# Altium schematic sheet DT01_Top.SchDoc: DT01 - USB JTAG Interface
size A4; Organization: Altium Limited.; Address1: Level 3, 12a Rodborough Rd; Address2: Frenchs Forest 2086; Address3: NSW; Address4: AUSTRALIA; DocumentNumber: 1; Revision: 01; SheetNumber: 1; SheetTotal: 12; PageSetup: Record=PageOptions|CenterHorizontal=True|CenterVertical=True|PrintScale=0.50|XCorrection=1.00|YCorrection=1.00|PrintKind=0|BorderSize=5000000|LeftOffset=0|BottomOffset=0|Orientation=2|PaperLength=1000|PaperWidth=1000|Scale=100|PaperSource=7|PrintQuality=600|MediaType=1|DitherType=10|PaperKind=A3 (297 x 420 mm)|PrintScaleMode=1
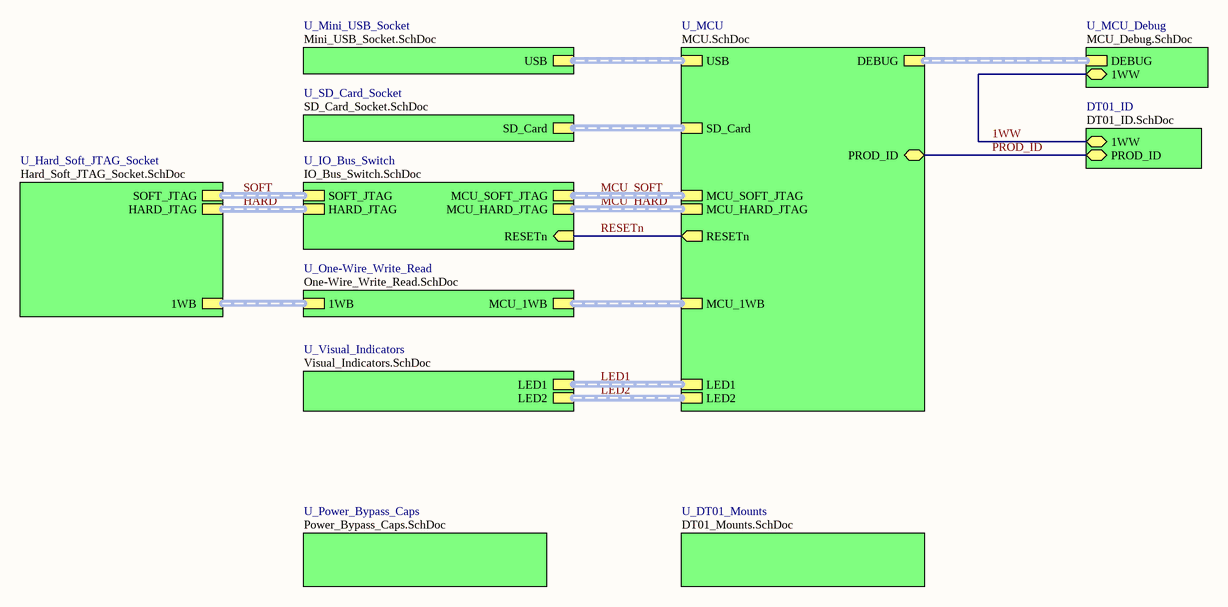
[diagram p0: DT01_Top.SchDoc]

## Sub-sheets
DT01_ID = DT01_ID.SchDoc: PROD_ID (bidir), 1WW (bidir)
U_DT01_Mounts = DT01_Mounts.SchDoc: no entries
U_Hard_Soft_JTAG_Socket = Hard_Soft_JTAG_Socket.SchDoc: 1WB (harness 1WB_Write_Read), SOFT_JTAG (harness JTAG), HARD_JTAG (harness JTAG)
U_IO_Bus_Switch = IO_Bus_Switch.SchDoc: SOFT_JTAG (harness JTAG), HARD_JTAG (harness JTAG), MCU_SOFT_JTAG (harness JTAG), MCU_HARD_JTAG (harness JTAG), RESETn (in)
U_MCU = MCU.SchDoc: USB (harness USB), RESETn (out), DEBUG (harness LOCAL_JTAG), MCU_SOFT_JTAG (harness JTAG), MCU_HARD_JTAG (harness JTAG), MCU_1WB (harness MCU_1WB_R_W), LED1 (harness RGB_LED), LED2 (harness RGB_LED), PROD_ID (bidir), SD_Card (harness SD Card)
U_MCU_Debug = MCU_Debug.SchDoc: DEBUG (harness LOCAL_JTAG), 1WW (bidir)
U_Mini_USB_Socket = Mini_USB_Socket.SchDoc: USB (harness USB)
U_One-Wire_Write_Read = One-Wire_Write_Read.SchDoc: 1WB (harness 1WB_Write_Read), MCU_1WB (harness MCU_1WB_R_W)
U_Power_Bypass_Caps = Power_Bypass_Caps.SchDoc: no entries
U_SD_Card_Socket = SD_Card_Socket.SchDoc: SD_Card (harness SD Card)
U_Visual_Indicators = Visual_Indicators.SchDoc: LED1 (harness RGB_LED), LED2 (harness RGB_LED)

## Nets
1WW: sheet DT01_ID/1WW, sheet U_MCU_Debug/1WW
PROD_ID: sheet U_MCU/PROD_ID, sheet DT01_ID/PROD_ID
RESETn: sheet U_MCU/RESETn, sheet U_IO_Bus_Switch/RESETn

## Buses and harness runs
harness HARD = sheet U_Hard_Soft_JTAG_Socket/HARD_JTAG = sheet U_IO_Bus_Switch/HARD_JTAG
harness LED1 = sheet U_MCU/LED1 = sheet U_Visual_Indicators/LED1
harness LED2 = sheet U_MCU/LED2 = sheet U_Visual_Indicators/LED2
harness MCU_HARD = sheet U_IO_Bus_Switch/MCU_HARD_JTAG = sheet U_MCU/MCU_HARD_JTAG
harness MCU_SOFT = sheet U_IO_Bus_Switch/MCU_SOFT_JTAG = sheet U_MCU/MCU_SOFT_JTAG
harness sheet U_Hard_Soft_JTAG_Socket/1WB = sheet U_One-Wire_Write_Read/1WB
harness sheet U_MCU/DEBUG = sheet U_MCU_Debug/DEBUG
harness sheet U_MCU/MCU_1WB = sheet U_One-Wire_Write_Read/MCU_1WB
harness sheet U_MCU/SD_Card = sheet U_SD_Card_Socket/SD_Card
harness sheet U_MCU/USB = sheet U_Mini_USB_Socket/USB
harness SOFT = sheet U_Hard_Soft_JTAG_Socket/SOFT_JTAG = sheet U_IO_Bus_Switch/SOFT_JTAG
